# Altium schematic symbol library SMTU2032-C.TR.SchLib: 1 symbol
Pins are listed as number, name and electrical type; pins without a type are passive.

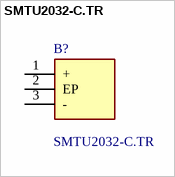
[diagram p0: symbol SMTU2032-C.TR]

## SMTU2032-C.TR
designator B?
Coin Cell Battery Holders SMT HOLDER ON T&R FOR CR2032-485/REEL; Manufacturer_Name: RENATA; Geometry.Height: 5.6mm
footprint SMTU2032CTR
pins: 1 +, 2 EP, 3 -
